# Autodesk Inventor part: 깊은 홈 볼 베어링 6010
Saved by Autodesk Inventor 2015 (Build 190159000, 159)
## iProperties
Created: 2026-05
Part Number: 깊은 홈 볼 베어링 6010
Material: 일반
Document SubType Name: Modeling
Designer: 104
Density: 1 g/cm^3
Appearance: 기본값
Author: 104
Author: jhkim
Description: 깊은 그루브 볼 베어링
Creation Date: 2026-04-27
Sending System: Autodesk Inventor 2027
Preprocessor: ST-DEVELOPER v20.1
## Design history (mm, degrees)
node "깊은 홈 볼 베어링 60101"
body "Solid1"
node "Solid1_1"
node "Solid1_2"
node "Solid1_3"
node "Solid1_4"
node "Solid1_5"
node "Solid1_6"
node "Solid1_7"
node "Solid1_8"
node "Solid1_9"
node "Solid1_10"
node "Solid1_11"
node "Solid1_12"
node "Solid1_13"
node "Solid1_14"
node "기준1"
node "기준2"
node "기준3"
node "기준4"
node "기준5"
node "기준6"
node "기준7"
node "기준8"
node "기준9"
node "기준10"
node "기준11"
node "기준12"
node "기준13"
node "기준14"
node "기준15"
